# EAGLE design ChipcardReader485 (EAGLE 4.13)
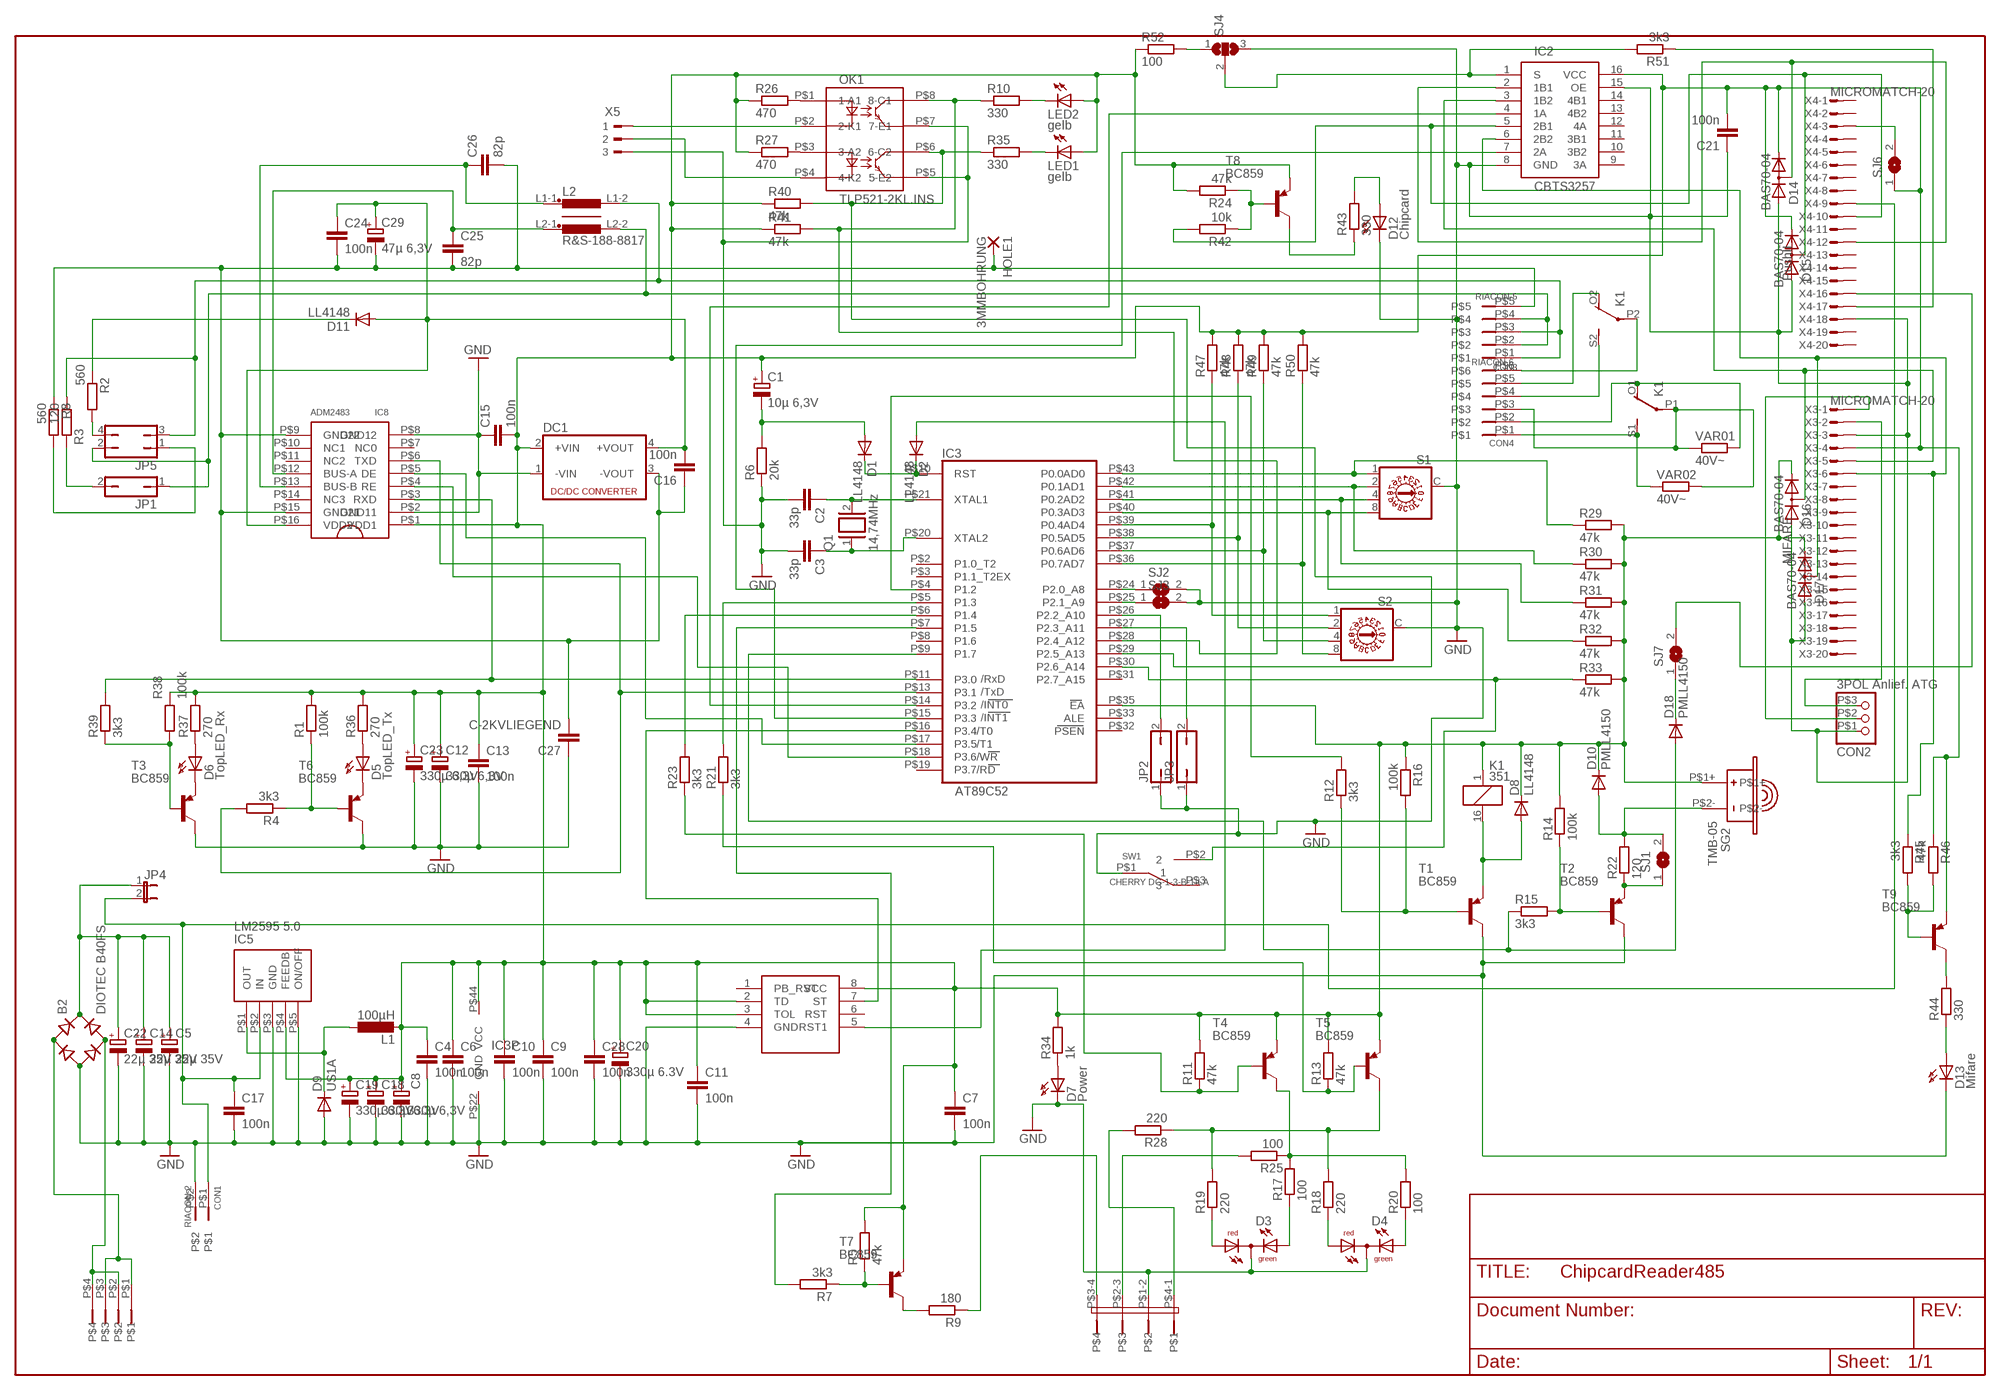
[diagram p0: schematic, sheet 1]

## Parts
B2  DIOTEC B40FS  DIOTECB40FS  [DIOTECB40FS]
C1  10µ 6,3V  CPOL-EUCT3216  [CT3216]
C2  33p  C-EUC0805  [C0805]
C3  33p  C-EUC0805  [C0805]
C4  100n  C-EUC0805  [C0805]
C5  22µ 35V  CPOL-EUCT7343  [CT7343]
C6  100n  C-EUC0805  [C0805]
C7  100n  C-EUC0805  [C0805]
C8  330µ 6,3V  CPOL-EUCT7343  [CT7343]
C9  100n  C-EUC0805  [C0805]
C10  100n  C-EUC0805  [C0805]
C11  100n  C-EUC0805  [C0805]
C12  330µ 6,3V  CPOL-EUCT7343  [CT7343]
C13  100n  C-EUC0805  [C0805]
C14  22µ 35V  CPOL-EUCT7343  [CT7343]
C15  100n  C-EUC0805  [C0805]
C16  100n  C-EUC0805  [C0805]
C17  100n  C-EUC0805  [C0805]
C18  330µ 6.3V  CPOL-EUCT7343  [CT7343]
C19  330µ 6.3V  CPOL-EUCT7343  [CT7343]
C20  330µ 6.3V  CPOL-EUCT7343  [CT7343]
C21  100n  C-EUC0805  [C0805]
C22  22µ 35V  CPOL-EUCT7343  [CT7343]
C23  330µ 6,3V  CPOL-EUCT7343  [CT7343]
C24  100n  C-EUC0805  [C0805]
C25  82p  C-EUC0805  [C0805]
C26  82p  C-EUC0805  [C0805]
C27  C-2KVLIEGEND  [C-2KV-LIEG]
C28  100n  C-EUC0805  [C0805]
C29  47µ 6,3V  CPOL-EUCT6032  [CT6032]
CON1  RIACON-2  [RIACON-2]
CON2  3POL Anlief. ATG  PROGRAMMIER-3POL  [PROGRAMMIER-3POL]
CON3  RIACON-5  [RIACON-5]
CON4  RIACON-6  [RIACON-6]
CON5  RIACON-4  [RIACON-4]
D1  LL4148  PMLL4150  [SOD80C]
D2  LL4148  PMLL4150  [SOD80C]
D3  DUOLED5MM  [DUOLED5MM]
D4  DUOLED5MM  [DUOLED5MM]
D5  TopLED_Tx  LED3MMPLCC-2  [TOPLED]
D6  TopLED_Rx  LED3MMPLCC-2  [TOPLED]
D7  Power  LED3MMPLCC-2  [TOPLED]
D8  LL4148  PMLL4150  [SOD80C]
D9  US1A  DIODE-SOD106A-R  [SOD106A-R]
D10  PMLL4150  [SOD80C]
D11  LL4148  PMLL4150  [SOD80C]
D12  Chipcard  LED3MMPLCC-2  [TOPLED]
D13  Mifare  LED3MMPLCC-2  [TOPLED]
D14  BAS70-04  DIODE_2CACA-SOT23  [SOT23]
D15  BAS70-04  DIODE_2CACA-SOT23  [SOT23]
D16  BAS70-04  DIODE_2CACA-SOT23  [SOT23]
D17  BAS70-04  DIODE_2CACA-SOT23  [SOT23]
D18  PMLL4150  [SOD80C]
DC1  NME  [NME]
HOLE1  3MMBOHRUNG  [3MMBOHRUNG]
IC2  CBTS3257  [SO16]
IC3  AT89C52  [PLCC44-SOCKEL]
IC4  MAX1232  [SO08]
IC5  LM2595 5.0  LM2595TO-263S  [LM2576S]
IC8  ADM2483  [SOIC16W]
JP1  JP1Q  [JP1]
JP2  JP1Q  [JP1]
JP3  JP1Q  [JP1]
JP4  JP1E  [JP1]
JP5  JP2Q  [JP2Q]
JP7  2X2ABGEWINKELT  [2X2ABGEWINKELT]
K1  351  [351]
L1  100µH  DO3316P  [DO3316P]
L2  R&S-188-8817  [R&S-188-8817]
LED1  gelb  LEDSMT1206  [1206]
LED2  gelb  LEDSMT1206  [1206]
OK1  TLP521-2KL.INS  [TLP521-2]
Q1  14,74MHz  XTAL/S  [QS]
R1  100k  R-EU_R0805  [R0805]
R2  560  R-EU_R0805  [R0805]
R3  120  R-EU_R0805  [R0805]
R4  3k3  R-EU_R0805  [R0805]
R5  47k  R-EU_R0805  [R0805]
R6  20k  R-EU_R0805  [R0805]
R7  3k3  R-EU_R0805  [R0805]
R8  560  R-EU_R0805  [R0805]
R9  180  R-EU_R0805  [R0805]
R10  330  R-EU_R0805  [R0805]
R11  47k  R-EU_R0805  [R0805]
R12  3k3  R-EU_R0805  [R0805]
R13  47k  R-EU_R0805  [R0805]
R14  100k  R-EU_R0805  [R0805]
R15  3k3  R-EU_R0805  [R0805]
R16  100k  R-EU_R0805  [R0805]
R17  100  R-EU_R0805  [R0805]
R18  220  R-EU_R0805  [R0805]
R19  220  R-EU_R0805  [R0805]
R20  100  R-EU_R0805  [R0805]
R21  3k3  R-EU_R0805  [R0805]
R22  120  R-EU_R0805  [R0805]
R23  3k3  R-EU_R0805  [R0805]
R24  47k  R-EU_R0805  [R0805]
R25  100  R-EU_R0805  [R0805]
R26  470  R-EU_R0805  [R0805]
R27  470  R-EU_R0805  [R0805]
R28  220  R-EU_R0805  [R0805]
R29  47k  R-EU_R0805  [R0805]
R30  47k  R-EU_R0805  [R0805]
R31  47k  R-EU_R0805  [R0805]
R32  47k  R-EU_R0805  [R0805]
R33  47k  R-EU_R0805  [R0805]
R34  1k  R-EU_R0805  [R0805]
R35  330  R-EU_R0805  [R0805]
R36  270  R-EU_R0805  [R0805]
R37  270  R-EU_R0805  [R0805]
R38  100k  R-EU_R0805  [R0805]
R39  3k3  R-EU_R0805  [R0805]
R40  47k  R-EU_R0805  [R0805]
R41  47k  R-EU_R0805  [R0805]
R42  10k  R-EU_R0805  [R0805]
R43  330  R-EU_R0805  [R0805]
R44  330  R-EU_R0805  [R0805]
R45  3k3  R-EU_R0805  [R0805]
R46  47k  R-EU_R0805  [R0805]
R47  47k  R-EU_R0805  [R0805]
R48  47k  R-EU_R0805  [R0805]
R49  47k  R-EU_R0805  [R0805]
R50  47k  R-EU_R0805  [R0805]
R51  3k3  R-EU_R0805  [R0805]
R52  100  R-EU_R0805  [R0805]
S1  P103  [P103]
S2  P103  [P103]
SG2  TMB-05  [TMB-05]
SJ1  SJ  [SJ]
SJ2  SJ  [SJ]
SJ3  SJ  [SJ]
SJ4  SJ2W  [SJ_2]
SJ6  SJ  [SJ]
SJ7  SJ  [SJ]
SW1  CHERRY DG-1-3-B-1-LA  CHERRI-MICROTASTER  [CHERRI-MICROTASTER]
T1  BC859  BCX71SMD  [SOT23]
T2  BC859  BCX71SMD  [SOT23]
T3  BC859  BCX71SMD  [SOT23]
T4  BC859  BCX71SMD  [SOT23]
T5  BC859  BCX71SMD  [SOT23]
T6  BC859  BCX71SMD  [SOT23]
T7  BC859  BCX71SMD  [SOT23]
T8  BC859  BCX71SMD  [SOT23]
T9  BC859  BCX71SMD  [SOT23]
VAR01  40V~  R-EU_M1206  [M1206]
VAR02  40V~  R-EU_M1206  [M1206]
X3  MICROMATCH-20  [MICROMATCH-20]
X4  MICROMATCH-20  [MICROMATCH-20]
X5  180-3  [180-3]

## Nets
1 [relais]: CON4.P$1 K1.S1(2:S) VAR02.1
2 [relais]: CON4.P$2 K1.O1(2:O) VAR01.2
3 [relais]: CON4.P$3 K1.P1(2:P) VAR01.1 VAR02.2
4 [relais]: CON4.P$4 K1.S2(3:S)
5 [relais]: CON4.P$5 K1.O2(3:O)
6 [relais]: CON4.P$6 K1.P2(3:P)
+B [power]: C17.1 CON1.P$1 IC5.P$2(IN) JP4.2 X4.9
+VO [power]: B2.PLUS(+) C5.+ C14.+ C22.+ JP4.1
A-OUT: C25.1 IC8.P$12(BUS-A) L2.L2-1(W2A)
B-OUT: C26.1 IC8.P$13(BUS-B) L2.L1-1(W1A)
BUS_A: CON3.P$2 CON3.P$4 JP1.1 JP5.2 L2.L2-2(W2E)
BUS_B: CON3.P$1 CON3.P$3 JP5.3 L2.L1-2(W1E) R3.1
CLOCK: IC2.4(1A) IC3.P$14(P3.2)
D3: IC3.P$28(P2.4_A12) OK1.P$8(8-C1) R10.1 R41.2
DATA: IC2.7(2A) IC3.P$15(P3.3)
GND [power]: B2.MINUS(-) C2.2 C3.2 C4.2 C5.- C6.2 C7.2 C8.- C9.2 C10.2 C11.2 C12.- C13.2 C14.- C15.1 C17.2 C18.- C19.- C20.- C21.1 C22.- C23.- C27.P$1 C28.2 CON1.P$2 CON2.P$1 D3.K(C) D4.K(C) D7.K(C) D9.A D12.K(C) D13.K(C) D14.1(A) D15.1(A) D16.1(A) D17.1(A) DC1.1(-VIN) IC2.8(GND) IC2.15(OE) IC3.P$22(GND) IC4.4(GND) IC5.P$3(GND) IC5.P$5(ON/OFF) IC8.P$2(GND11) IC8.P$8(GND12) JP2.1 JP3.1 JP7.P$1-2 OK1.P$5(5-E2) OK1.P$7(7-E1) R6.1 S1.C S2.C SJ2.2 SJ3.2 SJ4.3 SW1.P$1 T1.3(C) T2.3(C) T3.3(C) T6.3(C) X3.3 X4.18 X5.3
GND-BUS [gnd-bus]: C16.1 C24.2 C25.2 C26.2 C27.P$2 C29.- CON3.P$5 DC1.3(-VOUT) HOLE1.P$1(P) IC8.P$9(GND22) IC8.P$15(GND21) R8.1
IN1 [in]: B2.WECHSEL1(AC1) CON5.P$1 CON5.P$3
IN2 [in]: B2.WECHSEL2(AC2) CON5.P$2 CON5.P$4
N$1: IC3.P$39(P0.4AD4) R47.1 S2.1
N$2: IC3.P$38(P0.5AD5) R48.1 S2.2
N$3: IC3.P$37(P0.6AD6) R49.1 S2.4
N$4: LED1.C R35.2
N$5: LED2.C R10.2
N$6: IC3.P$29(P2.5_A13) OK1.P$6(6-C2) R35.1 R40.2
N$7: IC3.P$4(P1.2) R12.2
N$8: JP7.P$3-4 R9.1
N$9: JP5.4 R2.2
N$10: OK1.P$1(1-A1) R26.2
N$11: C3.1 IC3.P$20(XTAL2) Q1.1
N$12: C2.1 IC3.P$21(XTAL1) Q1.2
N$13: D5.A R36.1
N$14: IC3.P$5(P1.3) R21.2
N$15: D5.K(C) T6.2(E)
N$16: JP1.2 R3.2
N$17: OK1.P$3(3-A2) R27.2
N$18: JP5.1 R8.2
N$19: IC3.P$36(P0.7AD7) R50.1 S2.8
N$20: D6.K(C) T3.2(E)
N$21: R11.1 R23.1 T4.1(B)
N$22: D6.A R37.1
N$23: R38.1 R39.1 T3.1(B)
N$24: IC2.1(S) R51.2 SJ4.2
N$25: IC3.P$30(P2.6_A14) R33.1 SW1.P$2
N$26: R12.1 R16.2 T1.1(B)
N$27: D1.C D2.C IC3.P$10(RST)
N$28: R22.1 SJ1.1 T2.2(E)
N$29: C1.- D1.A R6.2
N$30: D3.AR R19.1
N$31: D3.AG R17.1
N$32: R1.1 R4.1 T6.1(B)
N$34: D4.AR R18.1
N$35: IC3.P$6(P1.4) R23.2
N$36: D2.A IC4.5(RST1)
N$37: R14.1 R15.2 T2.1(B)
N$38: IC3.P$40(P0.3AD3) R32.1 S1.8
N$39: C16.2 C24.1 C29.+ D11.A DC1.4(+VOUT) IC8.P$16(VDD2)
N$40: R5.1 R7.1 T7.1(B)
N$41: D4.AG R20.1
N$42: IC3.P$16(P3.4/T0) IC4.7(ST)
N$43: IC3.P$41(P0.2AD2) R31.1 S1.4
N$44: D7.A R34.1
N$45: IC3.P$42(P0.1AD1) R30.1 S1.2
N$46: IC3.P$43(P0.0AD0) R29.1 S1.1
N$47: R13.1 R21.1 T5.1(B)
N$48: R18.2 R19.2 R28.1 T5.3(C)
N$49: R9.2 T7.3(C)
N$50: D18.A IC3.P$9(P1.7) R15.1
N$51: D10.A R22.2 SG2.P$2- SJ1.2
N$52: R17.2 R20.2 R25.1 T4.3(C)
N$53: IC3.P$7(P1.5) R7.2
N$54: IC3.P$24(P2.0_A8) SJ2.1
N$55: IC3.P$25(P2.1_A9) SJ3.1
N$56: IC3.P$18(P3.6/WR) IC8.P$4(RE)
N$57: D15.3(AC) IC2.5(2B1) R42.2 X4.10
N$58: JP7.P$2-3 R25.2
N$59: D14.3(AC) IC2.2(1B1) X4.12
N$60: IC3.P$26(P2.2_A10) JP2.2
N$61: IC3.P$27(P2.3_A11) JP3.2
N$62: D8.A K1.16 T1.2(E)
N$63: CON2.P$2 X3.1
N$64: JP7.P$4-1 R28.2
N$65: D17.3(AC) IC2.6(2B2) R45.1 X3.6
N$66: D16.3(AC) IC2.3(1B2) X3.5
N$67 [power]: SJ6.2 X4.3
N$68: R52.2 SJ4.1
N$69: D12.A R43.2
N$70: R43.1 T8.3(C)
N$71: R24.1 R42.1 T8.1(B)
N$72: SJ7.2 X4.16
N$73: D13.A R44.1
N$74: CON2.P$3 X3.2
N$75: R44.2 T9.3(C)
N$76: OK1.P$4(4-K2) X5.2
N$77: OK1.P$2(2-K1) X5.1
N$78: R45.2 R46.2 T9.1(B)
N$79: R51.1 X4.17
N$80: D11.C R2.1
N$81: D18.C SJ7.1
RX/TX: IC3.P$17(P3.5/T1) IC8.P$5(DE)
RXD: IC3.P$11(P3.0) IC8.P$3(RXD) R39.2
S1 [p]: D9.C IC5.P$1(OUT) L1.2
TXD: IC3.P$13(P3.1) IC8.P$6(TXD) R4.2
VCC [power]: C1.+ C4.1 C6.1 C7.1 C8.+ C9.1 C10.1 C11.1 C12.+ C13.1 C15.2 C18.+ C19.+ C20.+ C21.2 C23.+ C28.1 D8.C D10.C D14.2(C) D15.2(C) D16.2(C) D17.2(C) DC1.2(+VIN) IC2.16(VCC) IC3.P$35(EA) IC3.P$44(VCC) IC4.2(TD) IC4.3(TOL) IC4.8(VCC) IC5.P$4(FEEDB) IC8.P$1(VDD1) K1.1 L1.1 LED1.A LED2.A R1.2 R5.2 R11.2 R13.2 R14.2 R16.1 R24.2 R26.1 R27.1 R29.2 R30.2 R31.2 R32.2 R33.2 R34.2 R36.2 R37.2 R38.2 R40.1 R41.1 R46.1 R47.2 R48.2 R49.2 R50.2 R52.1 SG2.P$1+ SJ6.1 T4.2(E) T5.2(E) T7.2(E) T8.2(E) T9.2(E) X3.4
Unconnected: IC2.9(3A) IC2.10(3B2) IC2.11(3B1) IC2.12(4A) IC2.13(4B2) IC2.14(4B1) IC3.P$2(P1.0_T2) IC3.P$3(P1.1_T2EX) IC3.P$8(P1.6) IC3.P$19(P3.7/RD) IC3.P$31(P2.7_A15) IC3.P$32(PSEN) IC3.P$33(ALE) IC4.1(PB_RST) IC4.6(RST) IC8.P$7(NC0) IC8.P$10(NC1) IC8.P$11(NC2) IC8.P$14(NC3) SW1.P$3 X3.7 X3.8 X3.9 X3.10 X3.11 X3.12 X3.13 X3.14 X3.15 X3.16 X3.17 X3.18 X3.19 X3.20 X4.1 X4.2 X4.4 X4.5 X4.6 X4.7 X4.8 X4.11 X4.13 X4.14 X4.15 X4.19 X4.20

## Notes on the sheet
- PushII
- MIFARE

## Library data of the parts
B2 = rectifier:DIOTECB40FS
C1 C5 C8 C12 C14 C18-C20 C22 C23 C29 = rcl:CPOL-EU: POLARIZED CAPACITOR, European symbol
C2-C4 C6 C7 C9-C11 C13 C15-C17 C21 C24-C26 C28 = rcl:C-EU: CAPACITOR, European symbol
C27 = capacitor-wima:C-2KV
CON1 = con-riacon:RIACON-2
CON2 = pinhead:PROGRAMMIER-3POL
CON3 = con-riacon:RIACON-5
CON4 = con-riacon:RIACON-6
CON5 = con-riacon:RIACON-4
D1 D2 D8 D10 D11 D18 = diode:PMLL4150: DIODE
D3 D4 = led:DUOLED5MM: DUO LED 2 colors, 5 mm, round
D5-D7 D12 D13 = led:LED3MM: LED
D9 = diode:DIODE-: DIODE
D14-D17 = diode:DIODE_2CACA-: 2 Diodes - Cathode-Anode|Cathode-Anode
DC1 = dc-dc-converter:NME: DC-DC CONVERTER
HOLE1 = wirepad:3MMBOHRUNG
IC2 = PHILIPS:CBTS3257: Der Switcher
IC3 = atmel:AT89C*52: MICROCONTROLLER 8 Kbytes FLASH; 2K Bytes EEPROM Compatible with MCS-51 Products at89s8252.pdf
IC4 = watch:MAX1232
IC5 = National_Semiconductor:LM2595: SIMPLE SWITCHER® Power Converter 150 kHz 1A Step-Down Voltage Regulator
IC8 = analog-devices:ADM2483: Isolated RS-485 Transciver with I-Coupler
JP1-JP3 = jumper:JP1Q: JUMPER
JP4 = jumper:JP1E: JUMPER
JP5 = jumper:JP2Q: JUMPER
JP7 = jumper:2X2ABGEWINKELT
K1 = relay:351: RELAY 2 x switch, Omron
L1 = inductor-coilcraft:DO3316P: COILCRAFT
L2 = inductors:R&S-188-8817: Filterspule von R&S
LED1 LED2 = led:LED: LED
OK1 = optocoupler:TLP521-2
Q1 = special:XTAL/S: CRYSTAL
R1-R52 VAR01 VAR02 = rcl:R-EU_: RESISTOR, European symbol
S1 S2 = switch-dil:P103: DIL/CODE SWITCH
SG2 = buzzer:TMB-05
SJ1-SJ3 SJ6 SJ7 = jumper:SJ: SMD solder JUMPER
SJ4 = jumper:SJ2W: SMD solder JUMPER
SW1 = switch:CHERRI-MICROTASTER
T1-T9 = transistor-pnp:BCX71SMD: PNP Transistor
X3 X4 = con-amp-micromatch:MICROMATCH-20: MicroMaTch 20 9-215464-0 / 2-215464-0 Drawing Number C-215464 DDEController.pdf
X5 = con-weidmueller-sl35:180-3: WEIDMUELLER CLAMP CONNECTOR

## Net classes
1 relais: width 0.61 mm
2 power: width 0.508 mm
3 p: width 0.66 mm
4 in: width 0.559 mm
5 gnd-bus: width 0.406 mm

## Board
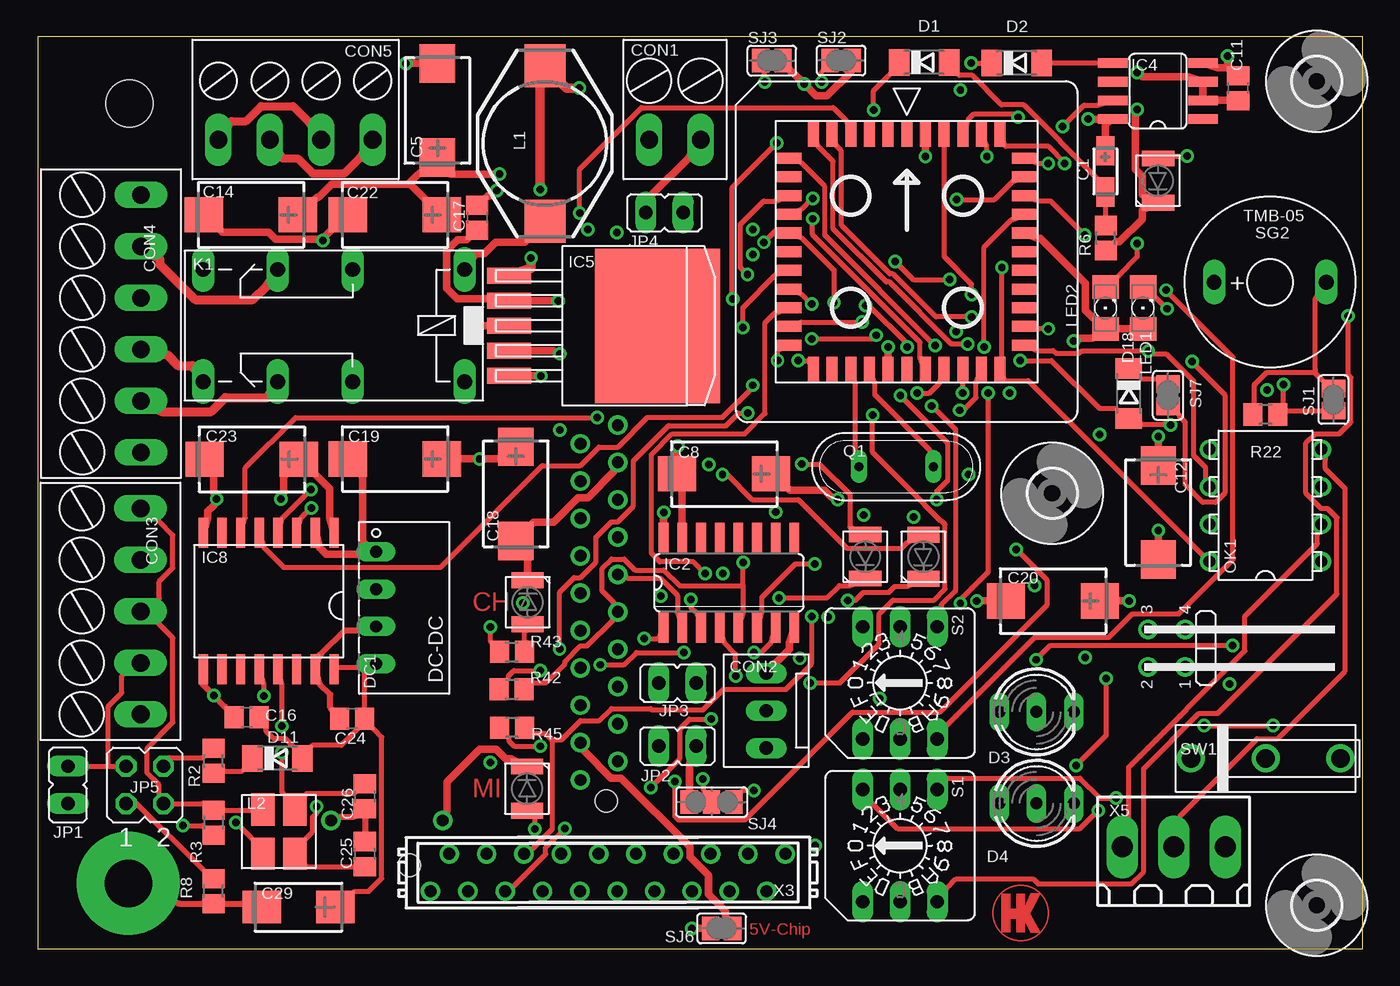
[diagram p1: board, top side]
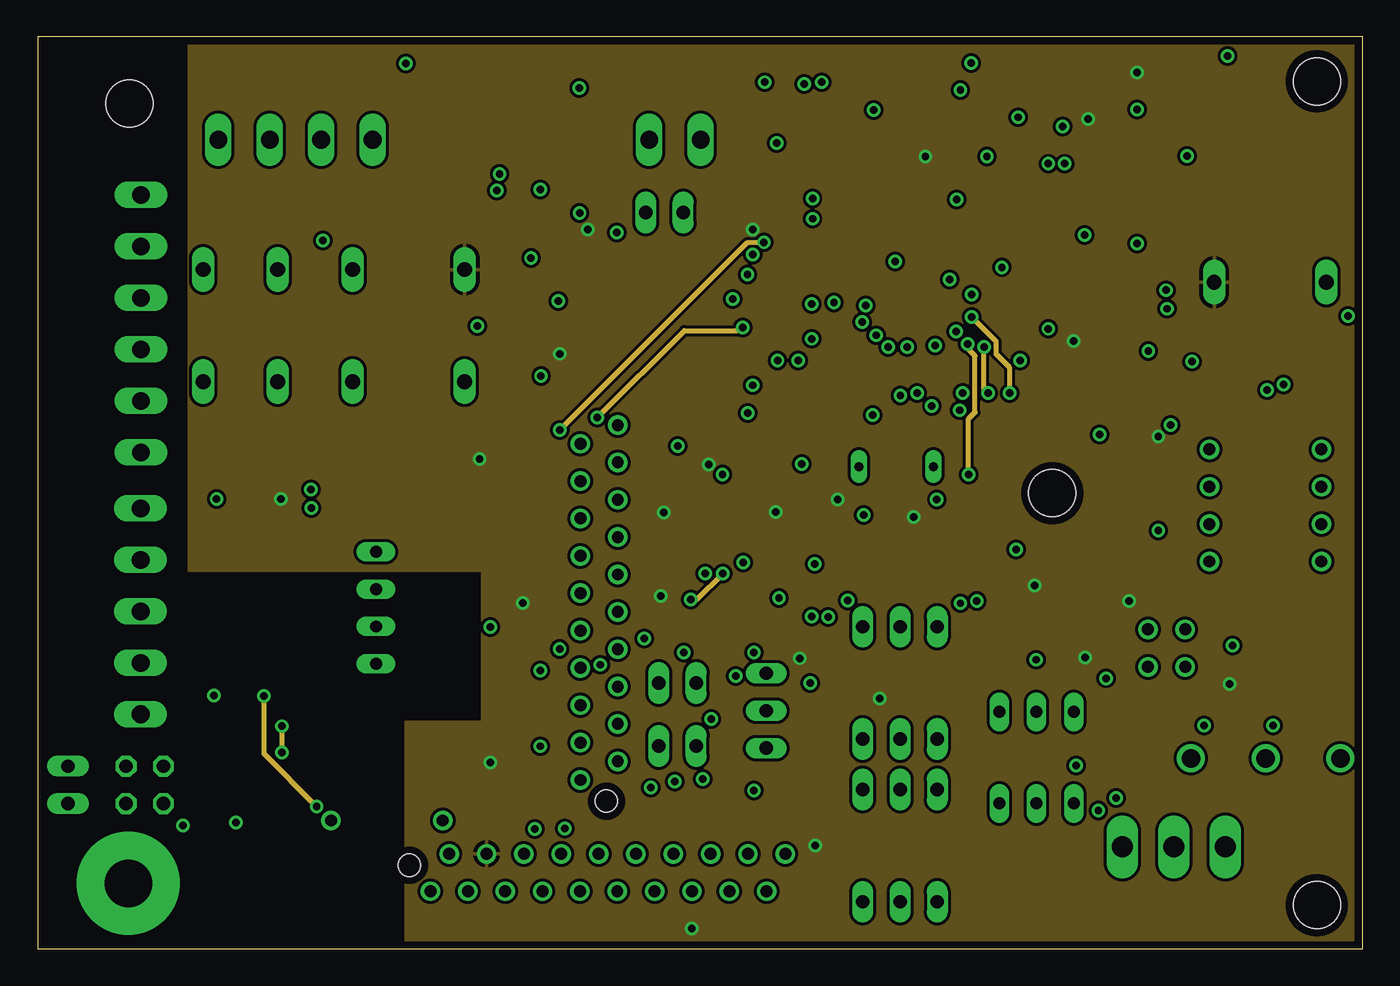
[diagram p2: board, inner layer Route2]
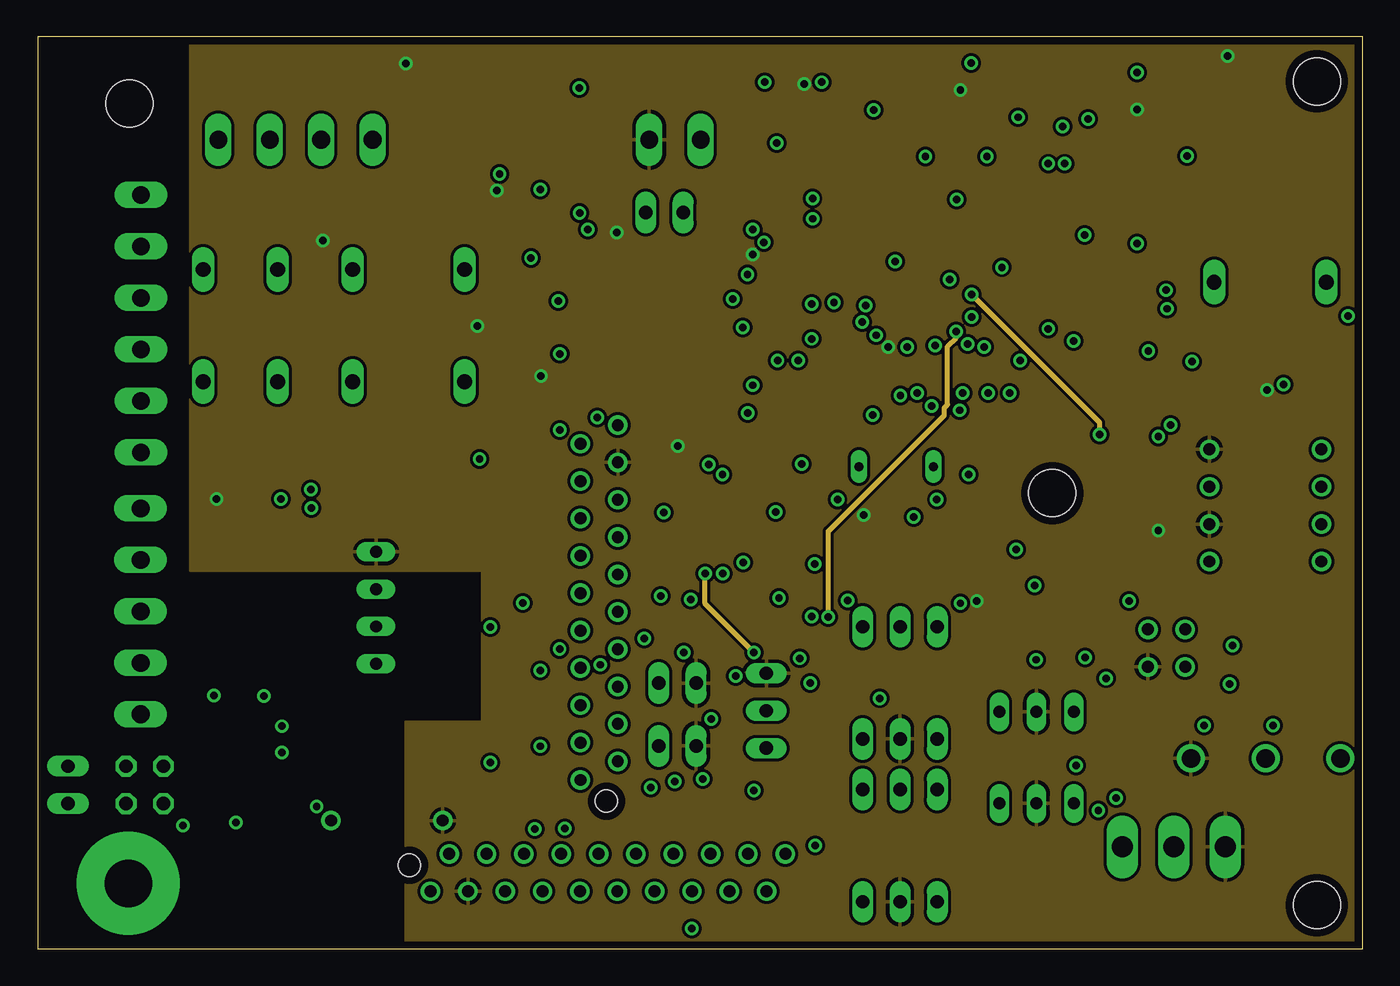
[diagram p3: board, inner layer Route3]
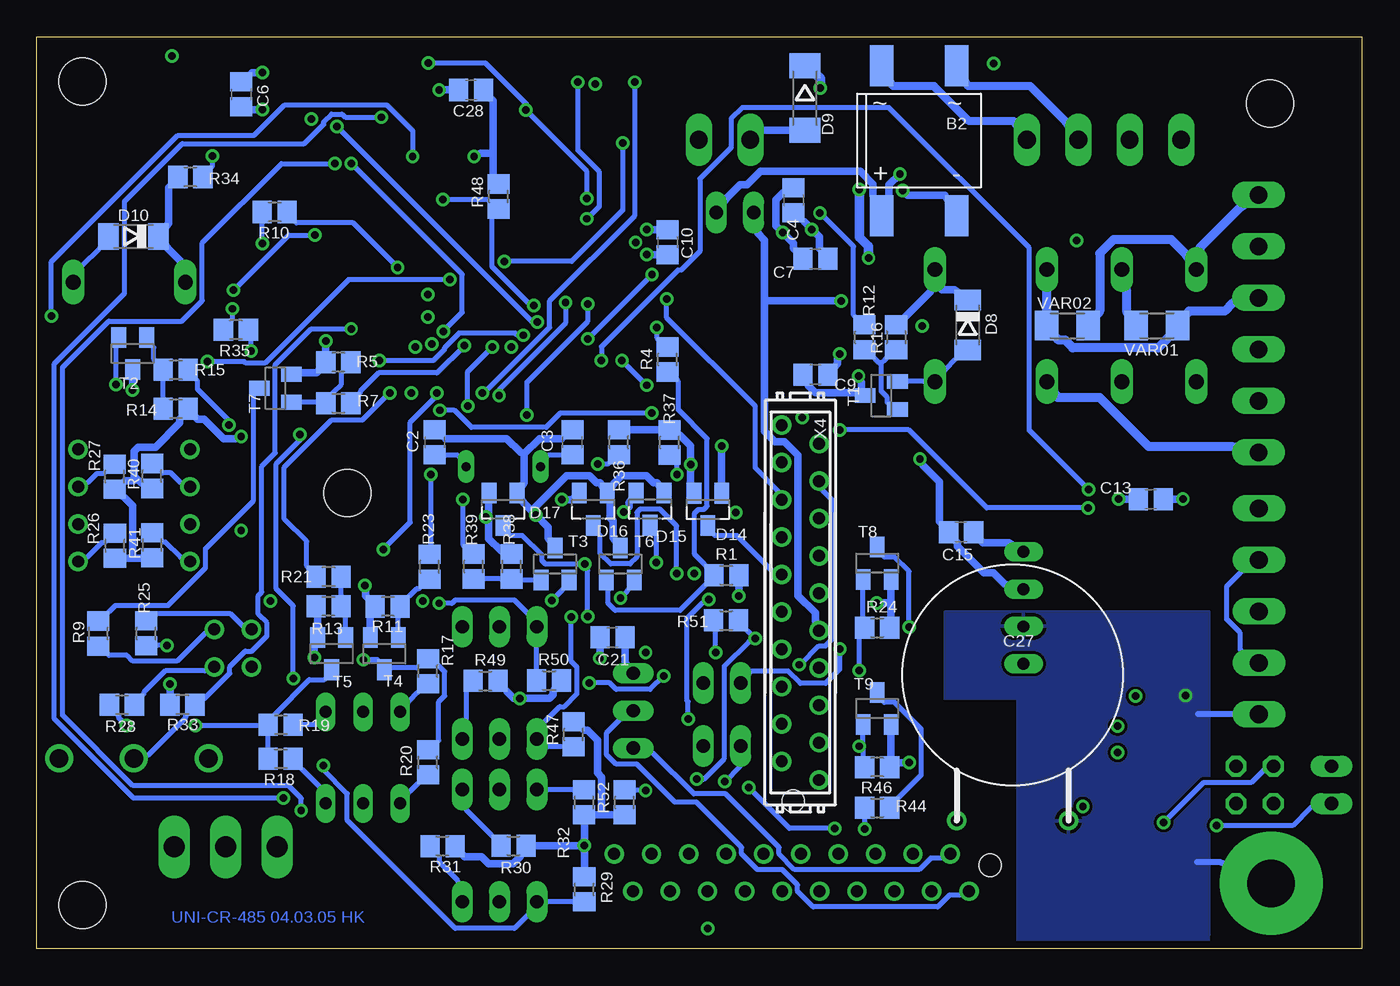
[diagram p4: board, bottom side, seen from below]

Size 90.12 x 62 mm. Coordinates in mm from the lower left corner, seen from the top.
Outline: 90.12,0 90.12,62 0,62 0,0 90.12,0
Copper layers (1+2+3*16): Top 0.035mm / dielectric 0.35mm / Route2 0.035mm / dielectric 0.71mm / Route3 0.035mm / dielectric 0.35mm / GND 0.035mm
Design rules "default": minimum track width 14mil, minimum drill 20mil, track to track 8mil, track to pad 8mil, pad to pad 8mil, via to via 8mil, smd to smd 8mil, copper to edge 20mil, drill to drill 12mil, minimum pad ring 10mil, minimum via ring 8mil, stop-mask expansion 4mil, vias tented up to drill 0mil, thermal gap 10mil
Holes 3.2 mm at 6.25,57.47
tRestrict: area 0.9,53.3 to 10.1,62; area 0,0.1 to 2.5,8.5; area 2.6,0 to 10.3,0.9
bRestrict: area 1,53.3 to 10.2,62; area 0,0.1 to 2.5,8.5; area 2.6,0 to 10.3,0.9

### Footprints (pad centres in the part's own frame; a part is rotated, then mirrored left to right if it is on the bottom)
DIOTECB40FS = smd 1.6 x 2.8: MINUS 2.55,-5.1; PLUS -2.55,-5.1; WECHSEL1 -2.55,5.1; WECHSEL2 2.55,5.1
CT3216 = smd 2 x 1.2: + 1.4,0; - -1.4,0
C0805 = smd 1.3 x 1.5: 1 -0.85,0; 2 0.85,0
CT7343 = smd 2.6 x 2.4: + 3.2,0; - -3.2,0
C-2KV-LIEG = drill 0.813 round: P$1 -3.8,-0.4; P$2 3.8,-0.4
CT6032 = smd 2.6 x 2.2: + 2.5,0; - -2.5,0
RIACON-2 = drill 1.2 long: P$1 0,1.75; P$2 0,-1.75
PROGRAMMIER-3POL = drill 0.9 long: P$1 0,2.54; P$2 0,0; P$3 0,-2.54
RIACON-5 = drill 1.2 long: P$1 0,7; P$2 0,3.5; P$3 0,0; P$4 0,-3.5; P$5 0,-7
RIACON-6 = drill 1.2 long: P$1 0,8.75; P$2 0,5.25; P$3 0,1.75; P$4 0,-1.75; P$5 0,-5.25; P$6 0,-8.75
RIACON-4 = drill 1.2 long: P$1 0,5.25; P$2 0,1.75; P$3 0,-1.75; P$4 0,-5.25
SOD80C = smd 1.4 x 1.8: A 1.7,0; C -1.7,0
DUOLED5MM = drill 0.813 long: AG -2.54,0; AR 2.54,0; K 0,0
TOPLED = smd 2.184 x 1.067: A 0,1.5; K 0,-1.5
SOD106A-R = smd 1.7 x 2.1: A 2.2,0; C -2.2,0
SOT23 = smd 1 x 1.4: 1 -0.95,-1.1; 2 0.95,-1.1; 3 0,1.1
NME = drill 0.813 long: 1 0,3.81; 2 0,1.27; 3 0,-1.27; 4 0,-3.81
3MMBOHRUNG = drill 3.2 pad 7 round: P$1 0,0
SO16 = smd 0.66 x 2.032: 1 -4.445,-3.073; 2 -3.175,-3.073; 3 -1.905,-3.073; 4 -0.635,-3.073; 5 0.635,-3.073; 6 1.905,-3.073; 7 3.175,-3.073; 8 4.445,-3.073; 9 4.445,3.073; 10 3.175,3.073; 11 1.905,3.073; 12 0.635,3.073; 13 -0.635,3.073; 14 -1.905,3.073; 15 -3.175,3.073; 16 -4.445,3.073
PLCC44-SOCKEL = smd 0.75 x 1.8: P$1 0,8.05; P$2 -1.27,8.05; P$3 -2.54,8.05; P$4 -3.81,8.05; P$5 -5.08,8.05; P$6 -6.35,8.05; P$18 -6.35,-8.05; P$19 -5.08,-8.05; P$20 -3.81,-8.05; P$21 -2.54,-8.05; P$22 -1.27,-8.05; P$23 0,-8.05; P$24 1.27,-8.05; P$25 2.54,-8.05; P$26 3.81,-8.05; P$27 5.08,-8.05; P$28 6.35,-8.05; P$40 6.35,8.05; P$41 5.08,8.05; P$42 3.81,8.05; P$43 2.54,8.05; P$44 1.27,8.05 | smd 1.8 x 0.75: P$7 -8.05,6.35; P$8 -8.05,5.08; P$9 -8.05,3.81; P$10 -8.05,2.54; P$11 -8.05,1.27; P$12 -8.05,0; P$13 -8.05,-1.27; P$14 -8.05,-2.54; P$15 -8.05,-3.81; P$16 -8.05,-5.08; P$17 -8.05,-6.35; P$29 8.05,-6.35; P$30 8.05,-5.08; P$31 8.05,-3.81; P$32 8.05,-2.54; P$33 8.05,-1.27; P$34 8.05,0; P$35 8.05,1.27; P$36 8.05,2.54; P$37 8.05,3.81; P$38 8.05,5.08; P$39 8.05,6.35
SO08 = smd 0.66 x 2.032: 1 -1.905,-3.073; 2 -0.635,-3.073; 3 0.635,-3.073; 4 1.905,-3.073; 5 1.905,3.073; 6 0.635,3.073; 7 -0.635,3.073; 8 -1.905,3.073
LM2576S = smd 3 x 1.067: P$1 6.38,-3.4; P$2 6.38,-1.7; P$3 6.38,0; P$4 6.38,1.7; P$5 6.38,3.4 | smd 8.5 x 10.5: P$6 -3.72,0
SOIC16W = smd 0.635 x 2.032: P$1 -4.445,-4.645; P$2 -3.175,-4.645; P$3 -1.905,-4.645; P$4 -0.635,-4.645; P$5 0.635,-4.645; P$6 1.905,-4.645; P$7 3.175,-4.645; P$8 4.445,-4.645; P$9 4.445,4.645; P$10 3.175,4.645; P$11 1.905,4.645; P$12 0.635,4.645; P$13 -0.635,4.645; P$14 -1.905,4.645; P$15 -3.175,4.645; P$16 -4.445,4.645
JP1 = drill 0.914 long: 1 0,-1.27; 2 0,1.27
JP2Q = drill 0.914 octagon: 1 -1.27,-1.27; 2 -1.27,1.27; 3 1.27,-1.27; 4 1.27,1.27
2X2ABGEWINKELT = drill 0.813 round: P$1-2 -1.27,2.54; P$2-3 1.27,2.54; P$3-4 1.27,0; P$4-1 -1.27,0
351 = drill 1.016 long: 1 -3.81,-3.81; 16 -3.81,3.81; O1 8.89,-3.81; O2 8.89,3.81; P1 3.81,-3.81; P2 3.81,3.81; S1 13.97,-3.81; S2 13.97,3.81
DO3316P = smd 2.92 x 2.79: 1 -5.28,0; 2 5.28,0
R&S-188-8817 = smd 2.2 x 1.6: L1-1 -1.5,1.1; L1-2 -1.5,-1.1; L2-1 1.5,1.1; L2-2 1.5,-1.1
1206 = smd 1.6 x 1.803: A -1.422,0; C 1.422,0
TLP521-2 = drill 0.813 round: P$1 -3.81,-3.81; P$2 -1.27,-3.81; P$3 1.27,-3.81; P$4 3.81,-3.81; P$5 3.81,3.81; P$6 1.27,3.81; P$7 -1.27,3.81; P$8 -3.81,3.81
QS = drill 0.61 long: 1 -2.54,0; 2 2.54,0
R0805 = smd 1.3 x 1.5: 1 -0.85,0; 2 0.85,0
P103 = drill 0.914 long: 1 3.81,-2.54; 2 -3.81,2.54; 4 3.81,2.54; 8 -3.81,-2.54; C 3.81,0; C1 -3.81,0
TMB-05 = drill 1.016 long: P$1+ -3.81,0; P$2- 3.81,0
SJ = smd 1.168 x 1.6: 1 -0.762,0; 2 0.762,0
SJ_2 = smd 1.168 x 1.6: 1 -1.524,0; 2 0,0; 3 1.524,0
CHERRI-MICROTASTER = drill 1.27 round: P$1 -5.08,0; P$2 0,0; P$3 5.08,0
3,2 = hole 3.2: 0,0
M1206 = smd 1.6 x 2: 1 -1.4,0; 2 1.4,0
MICROMATCH-20 = drill 0.813 round: 1 12.065,1.27; 2 10.795,-1.27; 3 9.525,1.27; 4 8.255,-1.27; 5 6.985,1.27; 6 5.715,-1.27; 7 4.445,1.27; 8 3.175,-1.27; 9 1.905,1.27; 10 0.635,-1.27; 11 -0.635,1.27; 12 -1.905,-1.27; 13 -3.175,1.27; 14 -4.445,-1.27; 15 -5.715,1.27; 16 -6.985,-1.27; 17 -8.255,1.27; 18 -9.525,-1.27; 19 -10.795,1.27; 20 -12.065,-1.27 | hole 1.5: 13.5,-0.5
180-3 = drill 1.422 long: 1 -3.5,0; 2 0,0; 3 3.5,0

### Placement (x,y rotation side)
B2  30.12,54.94 0 bottom
C1  72.62,52.85 90 top
C2  63.06,34.43 90 bottom
C3  53.69,34.43 90 bottom
C4  38.65,50.89 90 bottom
C5  27.19,56.99 270 top
C6  76.21,58.09 270 bottom
C7  37.16,46.9 180 bottom
C8  46.68,32.29 0 top
C9  37.16,39.03 180 bottom
C10  47.22,48.03 270 bottom
C11  81.64,58.51 90 top
C12  76.22,29.66 90 top
C13  14.36,30.56 0 bottom
C14  14.51,49.9 0 top
C15  27.26,28.33 180 bottom
C16  14.23,15.74 0 top
C17  29.9,49.7 90 top
C18  32.53,30.93 90 top
C19  24.3,33.3 0 top
C20  69.05,23.65 0 top
C21  50.97,21.17 180 bottom
C22  24.3,49.9 0 top
C23  14.57,33.28 0 top
C24  21.39,15.65 180 top
C25  22.26,6.44 90 top
C26  22.26,10.36 270 top
C27  23.76,9.12 0 bottom
C28  60.59,58.38 180 bottom
C29  17.75,2.83 0 top
CON1  43.35,55 270 top
CON2  49.56,16.19 0 top
CON3  7.01,22.94 0 top
CON4  7.04,42.5 0 top
CON5  17.54,55 270 top
D1  60.28,60.26 0 top
D2  66.57,60.22 0 top
D3  67.94,16.11 0 top
D4  67.94,9.89 0 top
D5  56.29,26.66 0 top
D6  60.24,26.65 0 top
D7  76.2,52.22 0 top
D8  26.8,42.41 270 bottom
D9  37.88,57.83 270 bottom
D10  83.54,48.43 180 bottom
D11  16.3,12.95 0 top
D12  33.33,23.56 180 top
D13  33.28,10.89 180 top
D14  44.48,29.87 180 bottom
D15  48.41,29.89 180 bottom
D16  52.28,29.88 180 bottom
D17  58.41,29.88 180 bottom
D18  74.21,37.74 270 top
DC1  23.02,23.18 0 top
HOLE1  6.18,4.44 0 top
IC2  47.02,24.89 0 top
IC3  59.11,47.39 0 top
IC4  76.19,58.31 90 top
IC5  38.45,42.35 180 top
IC8  15.72,23.64 180 top
JP1  2.08,11.14 180 top
JP2  43.52,13.79 90 top
JP3  43.52,18.06 90 top
JP4  42.64,50.04 90 top
JP5  7.29,11.14 0 top
JP7  78.05,20.44 90 top
K1  25.23,42.37 180 top
L1  34.5,54.75 90 top
L2  16.41,7.96 270 top
LED1  75.17,43.56 90 top
LED2  72.63,43.56 90 top
OK1  83.5,30.14 90 top
Q1  58.38,32.78 0 top
R1  43.22,25.4 0 bottom
R2  11.97,12.77 90 top
R3  11.97,8.57 270 top
R4  47.22,40.06 90 bottom
R5  69.61,39.88 180 bottom
R6  72.64,48.32 90 top
R7  69.61,37.09 0 bottom
R8  11.96,3.92 90 top
R9  85.93,21.43 90 bottom
R10  73.94,50.09 180 bottom
R11  66.25,23.27 180 bottom
R12  33.84,41.57 90 bottom
R13  70.28,23.28 180 bottom
R14  80.66,36.72 0 bottom
R15  80.67,39.35 180 bottom
R16  31.67,41.57 270 bottom
R17  63.52,18.87 90 bottom
R18  73.53,12.91 180 bottom
R19  73.53,15.22 180 bottom
R20  63.52,12.67 90 bottom
R21  70.27,25.29 180 bottom
R22  83.5,36.32 180 top
R23  63.41,25.97 90 bottom
R24  32.97,21.82 0 bottom
R25  82.68,21.44 90 bottom
R26  84.8,27.4 90 bottom
R27  84.82,32.1 90 bottom
R28  84.33,16.6 0 bottom
R29  52.89,4.04 90 bottom
R30  57.71,7 0 bottom
R31  62.53,6.98 0 bottom
R32  52.91,9.96 270 bottom
R33  80.22,16.6 180 bottom
R34  79.67,52.47 180 bottom
R35  76.58,42.08 180 bottom
R36  50.53,34.43 90 bottom
R37  47.09,34.42 90 bottom
R38  57.82,25.99 90 bottom
R39  60.42,25.99 90 bottom
R40  82.28,32.14 90 bottom
R41  82.26,27.44 90 bottom
R42  32.24,17.65 0 top
R43  32.26,20.18 0 top
R44  32.97,9.58 0 bottom
R45  32.26,15.04 180 top
R46  32.97,12.35 180 bottom
R47  53.61,14.58 90 bottom
R48  58.72,51.14 90 bottom
R49  59.61,18.21 0 bottom
R50  55.28,18.24 0 bottom
R51  43.24,22.32 0 bottom
R52  50.15,9.95 90 bottom
S1  58.65,7.01 270 top
S2  58.65,18.08 270 top
SG2  83.82,45.32 0 top
SJ1  88.13,37.33 90 top
SJ2  54.65,60.39 0 top
SJ3  49.94,60.38 0 top
SJ4  45.84,9.97 180 top
SJ6  46.52,1.39 0 top
SJ7  76.87,37.63 270 top
SW1  83.52,12.94 0 top
T1  32.69,37.61 90 bottom
T2  83.6,40.47 180 bottom
T3  54.87,26.16 0 bottom
T4  66.48,20.07 180 bottom
T5  70.07,20.07 180 bottom
T6  50.43,26.16 0 bottom
T7  73.89,38.11 90 bottom
T8  32.97,26.21 0 bottom
T9  32.97,16.33 0 bottom
U$1  [HK]  66.86,2.43 0 top
U$12  [3,2]  87,2.97 0 top
U$13  [3,2]  69,30.97 0 top
U$14  [3,2]  87,58.97 0 top
VAR01  13.95,42.36 180 bottom
VAR02  20.03,42.36 180 bottom
X3  38.79,5.18 180 top
X4  38.19,23.54 270 bottom
X5  77.26,6.93 0 top

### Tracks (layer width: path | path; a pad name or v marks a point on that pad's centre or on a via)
1
  GND 0.61: VAR02.1 17.84,43.35 17.84,47.27 16.9,48.21 12.98,48.21 12.02,47.25 K1.S1 11,47.69 8.32,50.37 CON4.P$1
2
  Top 0.61: CON4.P$2 8.32,46.87 8.32,46.53 10.72,44.13 14.64,44.13 15.6,45.09 K1.O1
  GND 0.61: VAR01.2 16.02,43.35 16.02,44.67 K1.O1
3
  GND 0.61: K1.P1 21.44,44.67 21.44,43.35 VAR02.2 20.64,41.37 20.18,41.37 19.66,40.85 13.86,40.85 13.34,41.37 VAR01.1 11.76,43.35 9.34,43.35 8.82,43.87 CON4.P$3
4
  Top 0.61: K1.S2 10.52,39.65 9.54,39.65 8.82,40.37 CON4.P$4
5
  Top 0.61: K1.O2 15.6,37.47 12.76,37.47 11.8,36.51 8.46,36.51 CON4.P$5
6
  GND 0.61: K1.P2 20.68,37.47 17.84,37.47 14.5,34.13 8.82,34.13 CON4.P$6
+B  (via drill 0.51)
  Top 0.508: C17.1 29.16,48.21 28.56,48.21 27.82,47.47 27.82,44.89 28.52,44.19 30.58,44.19 IC5.P$2 v35.42,44.05 | CON1.P$1 44.22,53.71 41.8,51.29 JP4.2
  GND 0.508: 40.62,44.05 40.62,48.17 41.08,48.63 JP4.2 | 40.62,44.05 40.62,35.17 39.92,34.47 39.26,34.47 38.34,33.55 38.34,23.99 37.18,22.83 37.18,22.29 X4.9 | 40.62,44.05 v35.42,44.05
+VO  (via drill 0.51)
  Top 0.508: 25.2,51.97 20,51.97 19.12,51.09 19,51.09 C14.+ | 25.2,51.97 25.74,52.51 C5.+ 28.1,52.67 v31.42,52.67 | C22.+ 26.22,51.09 25.44,51.87 25.2,51.97
  GND 0.508: JP4.1 43.2,51.03 42.3,51.93 41.82,51.93 40.9,52.85 34.12,52.85 33.26,51.99 33.26,51.23 B2.PLUS 32.16,51.23 32.16,51.93 v31.42,52.67
A-OUT  (via drill 0.51)
  Top 0.356: C25.1 18.3,5.59 L2.L2-1 18.3,7.55 18.7,7.95 18.7,8.95 18.98,9.23 v18.98,9.67 | v15.4,17.17 15.4,17.99 IC8.P$12
  Route2 0.356: v15.4,17.17 15.4,13.25 v18.98,9.67
B-OUT  (via drill 0.51)
  Top 0.356: C26.1 21.52,10.57 18.32,10.57 18.3,10.55 L2.L1-1 16.72,10.55 16.62,10.65 v16.62,13.33 | v16.62,15.13 16.62,17.99 IC8.P$13
  Route2 0.356: v16.62,13.33 v16.62,15.13
BUS_A  (via drill 0.51)
  Top 0.356: v13.48,8.59 14.52,7.55 L2.L2-2 | JP1.1 4.82,12.41 | 4.82,12.41 JP5.2 | CON3.P$4 5.74,18.55 5.74,17.41 4.82,16.49 4.82,12.41
  GND 0.356: CON3.P$4 8.28,20.33 8.28,21.47 9.2,22.39 9.2,24.63 8.28,25.55 CON3.P$2 | v13.48,8.59 10.78,11.29 7.54,11.29 6.72,12.11 JP5.2
BUS_B
  Top 0.356: L2.L1-2 14.52,9.43 12.7,9.43 R3.1 11.22,9.87 JP5.3 8.26,10.57 8.26,11.15 7.46,11.95 7.46,13.65 9.2,15.39 9.2,21.13 8.28,22.05 CON3.P$3 8.28,23.83 8.28,24.97 9.2,25.89 9.2,28.13 8.28,29.05 CON3.P$1
CLOCK  (via drill 0.51)
  Top 0.356: v52.64,43.83 51.98,44.49 51.94,44.49 IC3.P$14 | v56.78,36.29 56.78,33.75 60.32,30.21 60.32,30.19 61.44,29.07 61.5,29.07 61.72,28.85 61.72,24.45 60.98,23.71 58.18,23.71 57.22,22.75 57.22,20.71 54.58,18.07 v52.54,18.07 | v47.48,18.55 47.48,20.03 46.7,20.81 IC2.4
  GND 0.356: v52.64,43.83 52.64,42.67 56.78,38.53 v56.78,36.29 | v52.54,18.07 51.16,18.07 50.72,17.63 48.4,17.63 v47.48,18.55
D3  (via drill 0.51)
  Top 0.356: v65.58,46.33 65.58,40.23 IC3.P$28 65.82,38.63 67.38,38.63 79.22,26.79 OK1.P$8
  GND 0.356: R41.2 81.52,27.65 81.38,27.65 80.34,26.61 OK1.P$8 | v65.58,46.33 68.6,49.35 72.46,49.35 R10.1
DATA  (via drill 0.51)
  Top 0.356: v45.4,25.51 44.6,26.31 42.32,26.31 41.74,26.89 41.74,33.59 43.16,35.01 48.1,35.01 49.48,36.39 49.48,42.57 50.12,43.21 50.18,43.21 IC3.P$15 | v48.72,20.13 49.2,20.13 49.88,20.81 IC2.7
  Route3 0.356: v45.4,25.51 45.4,23.45 v48.72,20.13
GND  (via drill 0.51)
  Top 0.508: 19.34,48.23 16.2,48.23 15.72,48.71 12.6,48.71 C14.- | 19.34,48.23 19.82,48.71 C22.- | R6.1 73.38,48.05 73.58,48.05 75.12,49.59 75.12,50.19 D7.K 75.12,51.25 75.12,52.51 74.64,52.99 74.64,56.61 v74.78,57.05 | IC2.15 43.84,28.97 43.84,31.11 C8.- 43.48,33.73 v43.54,34.17 | SJ3.2 51.28,59.59 51.34,59.59 v52.14,58.79 52.94,57.99 53.7,57.99 55.3,59.59 SJ2.2 | D12.K 33.34,25.59 33.34,26.45 C18.- 33.72,29.01 35.08,29.01 36.74,30.67 37.42,30.67 39.18,32.43 X4.18 | 80.9,59.89 80.26,59.89 IC4.4 | 80.9,59.89 C11.2 | v31.24,51.55 30.88,51.19 30.64,51.19 C17.2 | SJ4.3 44.32,10.77 44.32,12.55 JP2.1 | IC3.P$22 v57.84,40.91 | IC8.P$8 11.58,29.29 11.58,29.73 11.98,30.13 v12.18,30.57 11.98,31.01 11.98,32.09 C23.- | IC8.P$2 19.2,27.27 19.38,27.09 19.38,27.07 19.64,26.81 21.7,26.81 DC1.1 22.1,27.65 22.1,32.11 C19.- | IC2.8 51.14,20.81 51.14,20.37 50.2,19.43 CON2.P$1 | D13.K 32.2,12.91 31.84,12.91 31.18,13.57 30.06,13.57 27.84,11.35 27.84,9.37 C27.P$1 | v25.04,60.19 C5.- | C20.- v63.88,23.65 | C12.- v76.22,28.43 | v80.94,60.69 80.94,60.13 80.9,59.89 | IC5.P$5 v34.24,38.95 | v29.9,42.35 IC5.P$3 | 19.34,48.23 v19.4,48.15
  GND 0.508: T6.3 50.92,27.95 50.92,29.11 51.12,29.31 51.12,30.29 D16.1 | D15.1 47.94,31.67 48.18,31.67 48.66,32.15 50.36,32.15 50.84,31.67 D16.1 | 56.47,29.78 56.98,30.29 D17.1 56.98,31.67 56.98,33.65 | 56.47,29.78 v56.18,29.49 55.36,28.67 55.36,27.95 T3.3 | 56.98,33.65 55.94,34.69 54.44,34.69 C3.2 | C2.2 62.32,34.69 58.16,34.69 57.22,33.75 56.98,33.65 | D16.1 51.82,31.67 52.04,31.67 52.52,32.15 54.1,32.15 56.47,29.78 | C7.2 38.66,47.63 38.66,47.97 v39.38,48.69 39.86,49.17 39.86,50.91 39.38,51.39 C4.2 | C9.2 37.64,38.29 37.16,37.81 34.48,37.81 T1.3 34.04,38.09 34.04,38.51 v34.24,38.95 | v43.54,34.17 43.54,31.65 D14.1 | v83.6,37.99 T2.3 | v12.18,30.57 12.88,30.57 C13.2 | C15.1 25.78,27.59 24,27.59 DC1.1 | C21.1 50.12,19.43 CON2.P$1 | v48.64,47.19 47.96,47.19 C10.2 | v62.76,58.39 62.08,58.39 C28.2 | v74.78,57.05 75.46,57.05 C6.2 | D9.A 38.92,55.63 40.72,55.63 CON1.P$2 | B2.MINUS 28.36,51.23 30.92,51.23 v31.24,51.55
  pour Route3: 25,0.47 25,15.47 30.2,15.47 30.2,25.67 10.36,25.67 10.36,61.47 89.5,61.47 89.5,0.47
GND-BUS  (via drill 0.51)
  Top 0.406: C16.1 12.74,16.47 v11.98,17.23 11.22,17.99 IC8.P$9 | C24.2 19.9,16.39 19.9,17.29 19.2,17.99 IC8.P$15 19.2,20.01 19.26,20.01 20.9,21.65 21.7,21.65 DC1.3 | C29.- 13.96,3.07 12.7,3.07 R8.1 11.22,3.07 9.66,3.07 HOLE1.P$1 | C25.2 C26.2 21.52,8.99 20.62,8.99 C27.P$2
  GND 0.406: 11.22,5.89 10.97,5.89 9.66,5.89 HOLE1.P$1 | CON3.P$5 8.8,15.95 11.16,15.95
  pour GND: 28.4,22.94 10.35,22.94 10.35,0.45 23.47,0.45 23.47,16.97 28.4,16.97
IN1
  Top 0.559: CON5.P$3 16.68,53.73 17.68,53.73 18.7,52.71 20.88,52.71 21.9,53.73 CON5.P$1
  GND 0.559: B2.WECHSEL1 31.88,58.65 29.1,58.65 26.72,56.27 23.68,56.27 CON5.P$1
IN2
  Top 0.559: CON5.P$4 13.18,56.27 14.18,56.27 15.2,57.29 17.38,57.29 18.4,56.27 CON5.P$2
  GND 0.559: B2.WECHSEL2 26.78,58.65 22.56,58.65 20.18,56.27 CON5.P$2
N$1  (via drill 0.51)
  Top 0.356: v68.74,53.37 68.04,53.37 IC3.P$39
  Route3 0.356: v62.48,41.97 62.48,41.55 61.88,40.95 61.88,36.99 61.66,36.77 61.66,36.27 53.78,28.39 v53.78,22.55
  GND 0.356: R47.1 55.4,13.73 S2.1 55.58,15.45 54.56,16.47 54.24,16.47 53.38,17.33 53.38,19.15 53.78,19.55 v53.78,22.55 | v68.74,53.37 68.7,53.37 61.18,45.85 61.18,43.27 v62.48,41.97
N$2  (via drill 0.51)
  Top 0.356: v62.5,50.93 65.06,50.93 66.28,52.15 IC3.P$38 | v60.82,36.91 62.44,35.29 62.44,24.37 61.48,23.41 61.48,23.31 S2.2 | v59.14,40.91 59.14,41.13 56.54,43.73 v56.32,43.73
  GND 0.356: v62.5,50.93 59.46,50.93 R48.1 59.16,49.65 59.16,46.37 56.52,43.73 v56.32,43.73 | v60.82,36.91 60.82,39.23 v59.14,40.91
N$3  (via drill 0.51)
  Top 0.356: v71.22,48.51 68.9,50.83 68.04,50.83 IC3.P$37 | v76.74,44.77 81.3,40.21 81.3,26.45 77.62,22.77 74.44,22.77 72.86,21.19 67.82,21.19 61.9,15.27 S2.4
  GND 0.356: R49.1 60.9,17.47 60.9,15.69 S2.4 | v71.22,48.51 73,48.51 v76.74,44.77
N$4  (via drill 0.51)
  Top 0.356: v76.8,43.51 76.06,44.25 LED1.C
  GND 0.356: v76.8,43.51 76.8,42.81 R35.2
N$5  (via drill 0.51)
  Top 0.356: v74.78,47.95 74.78,47.03 73.52,45.77 LED2.C
  GND 0.356: v74.78,47.95 74.78,49.35 R10.2
N$6  (via drill 0.51)
  Top 0.356: IC3.P$29 68.04,40.67 69.08,40.67 69.28,40.47 70.82,40.47 71,40.65 v75.54,40.65 75.98,40.45 76.76,40.45 78.6,38.61 78.6,33.55 79.42,32.73 79.42,32.07 OK1.P$6
  GND 0.356: R40.2 81.54,32.35 81,32.35 80.34,31.69 OK1.P$6 | v75.54,40.65 75.54,41.35 R35.1
N$7  (via drill 0.51)
  Top 0.356: v36.86,50.03 36.86,52.99 41.06,57.19 54.12,57.19 54.98,56.33 IC3.P$4
  GND 0.356: v36.86,50.03 34.58,47.75 34.58,43.07 R12.2
N$8
  GND 0.356: R9.1 85.2,19.95 83.98,19.95 83.58,19.55 80.58,19.55 78.7,21.43 JP7.P$3-4
N$9
  Top 0.356: R2.2 11.24,12.99 8.98,12.99 JP5.4
N$10
  GND 0.356: R26.2 85.54,27.61 85.7,27.61 86.68,26.63 OK1.P$1
N$11
  Top 0.356: IC3.P$20 55.62,38.45 55.62,33.89 Q1.1
  GND 0.356: C3.1 54.44,33.57 55.3,33.57 Q1.1
N$12
  Top 0.356: IC3.P$21 56.94,38.45 56.94,37.65 60.7,33.89 Q1.2
  GND 0.356: C2.1 62.32,33.55 61.48,33.55 Q1.2
N$13  (via drill 0.51)
  Top 0.356: v51.96,32.95 53.18,32.95 55.24,30.89 55.24,28.69 D5.A
  GND 0.356: v51.96,32.95 51.28,32.95 R36.1
N$14  (via drill 0.51)
  Top 0.356: v63.52,42.95 61.1,42.95 58.16,45.89 57.96,45.89 54.66,49.19 54.66,54.25 54.36,54.55 IC3.P$5
  Route2 0.356: v66.12,37.79 66.12,39.49 65.2,40.41 65.2,41.27 v63.52,42.95
  GND 0.356: v66.12,37.79 67.96,35.95 70.06,35.95 73.28,32.73 73.28,29.21 71.76,27.69 71.76,26.03 R21.2
N$15  (via drill 0.51)
  Top 0.356: v50.42,23.85 53.68,23.85 54.52,24.69 55.2,24.69 D5.K
  GND 0.356: v50.42,23.85 49.96,24.31 49.96,24.37 T6.2
N$16  (via drill 0.51)
  Top 0.356: v9.9,8.37 11.22,8.37 R3.2
  GND 0.356: v9.9,8.37 4.72,8.37 3.5,9.59 JP1.2
N$17
  GND 0.356: R27.2 85.56,32.31 86.04,32.31 86.66,31.69 OK1.P$3
N$18
  Top 0.356: R8.2 11.22,5.41 6.72,9.91 JP5.1
N$19  (via drill 0.51)
  Top 0.356: v64.36,40.91 64.36,47.69 66.24,49.57 66.28,49.57 IC3.P$36 | v64.66,37.77 64.66,25.63 62.76,23.73 v62.76,23.49
  Route2 0.356: v64.36,40.91 64.36,38.07 v64.66,37.77
  GND 0.356: R50.1 56.14,18.97 56.14,20.47 S2.8 56.82,22.89 57.64,23.71 61.66,23.71 61.88,23.49 v62.76,23.49
N$20  (via drill 0.51)
  Top 0.356: v55.08,23.69 55.62,23.69 56.16,24.23 57.9,24.23 58.3,24.63 59.16,24.63 D6.K
  GND 0.356: v55.08,23.69 54.4,24.37 T3.2
N$21
  GND 0.356: T4.1 65.54,21.85 65.54,22.53 R11.1 64.76,24.01 64.28,24.49 64.14,24.49 R23.1
N$22  (via drill 0.51)
  Top 0.356: v46.58,32.25 46.88,32.25 48.6,30.53 51.74,30.53 55.04,27.23 58.76,27.23 59.16,27.63 D6.A
  GND 0.356: v46.58,32.25 46.58,32.93 R37.1
N$23
  GND 0.356: T3.1 56.3,25.07 57.08,25.07 R38.1 58.56,25.15 59.68,25.15 R39.1
N$24  (via drill 0.51)
  Top 0.356: v41.26,21.09 42.26,21.09 IC2.1 | v45.24,11.53 45.3,11.47 45.3,10.77 SJ4.2
  GND 0.356: R51.2 41.76,21.59 v41.26,21.09 41.7,20.89 43.36,19.23 43.36,12.93 44.76,11.53 v45.24,11.53
N$25  (via drill 0.51)
  Top 0.356: v68.74,42.15 68.04,42.15 IC3.P$30
  GND 0.356: SW1.P$2 82.58,13.13 80,15.71 80,15.85 R33.1 78.72,17.01 77,18.73 77,19.17 75.94,20.23 75.5,20.23 74.46,21.27 74.46,22.15 75.06,22.75 75.06,24.01 74.82,24.25 74.82,32.79 73.9,33.71 73.9,39.71 71.46,42.15 v68.74,42.15
N$26
  GND 0.356: 32.68,39.83 32.68,37.89 32.28,37.49 32.28,37.15 T1.1 | 32.68,39.83 32.42,40.09 R16.2 | R12.1 33.1,40.09 32.84,39.83 32.68,39.83
N$27  (via drill 0.51)
  Top 0.356: v52.7,51.01 51.98,50.29 51.94,50.29 IC3.P$10 | v56.86,57.01 56.86,58.33 57.9,59.37 D1.C | v63.5,60.21 64.18,60.21 D2.C
  GND 0.356: v52.7,51.01 52.7,52.85 v56.86,57.01 56.84,57.45 59.6,60.21 v63.5,60.21
N$28  (via drill 0.51)
  Top 0.356: v84.72,38.35 84.72,37.05 R22.1 84.98,36.57 87.34,36.57 SJ1.1
  GND 0.356: v84.72,38.35 84.72,40.89 T2.2
N$29
  Top 0.356: R6.2 72.64,50.47 C1.- 72.04,52.39 67.06,57.37 65.56,57.37 63.56,59.37 62.68,59.37 D1.A
N$30
  GND 0.356: R19.1 72.04,15.23 71.14,15.23 D3.AR
N$31
  GND 0.356: R17.1 64.26,17.39 64.74,16.91 D3.AG
N$32
  GND 0.356: T6.1 51.26,24.37 51.26,23.49 50.78,23.01 46.36,23.01 44.7,24.67 R1.1 44.7,26.13 45.38,26.81 45.38,29.61 45.12,29.87 44.76,29.87 44.54,30.09 44.54,34.69 46.48,36.63 46.48,38.57 R4.1
N$34
  GND 0.356: R18.1 72.04,12.17 70.9,11.03 D4.AR
N$35  (via drill 0.51)
  Top 0.356: v63.24,41.11 62.14,41.11 57.92,45.33 57.72,45.33 54.1,48.95 54.1,53.53 53.08,54.55 IC3.P$6
  Route2 0.356: v63.32,32.25 63.32,36.03 63.76,36.47 63.76,40.31 63.24,40.83 v63.24,41.11
  GND 0.356: v63.32,32.25 63.32,27.45 R23.2
N$36
  Top 0.356: D2.A 68.96,60.23 72.12,60.23 IC4.5
N$37
  GND 0.356: T2.1 82.16,40.89 82.16,40.09 R15.2 81.52,37.45 R14.1
N$38  (via drill 0.51)
  Top 0.356: v69.86,53.37 69.86,53.45 68.76,54.55 65.82,54.55 IC3.P$40 | v72.14,9.41 70.9,8.17 58.48,8.17 56.82,9.83 S1.8
  GND 0.356: R32.1 53.64,10.81 55.4,10.81 S1.8 | v69.86,53.37 73.48,53.37 78.86,47.99 78.86,44.07 80.26,42.67 85.22,42.67 88.36,39.53 88.36,15.87 83.58,11.09 73,11.09 72.14,10.23 v72.14,9.41
N$39
  Top 0.356: C16.2 15.56,15.01 15.56,14.77 16.04,14.29 16.86,14.29 17.32,13.83 D11.A 18.68,13.83 20.66,13.83 21.74,14.91 C24.1 | C24.1 22.24,18.71 DC1.4 21.7,19.11 20.48,19.11 IC8.P$16 | C29.+ 21.54,3.91 22.52,3.91 23.4,4.79 23.4,14.39 22.88,14.91 C24.1
N$40
  GND 0.356: T7.1 72.1,37.17 71.1,37.17 R7.1 69.96,37.83 69.4,38.39 69.4,39.15 R5.1
N$41
  GND 0.356: R20.1 64.26,11.19 64.74,10.71 D4.AG
N$42  (via drill 0.51)
  Top 0.356: v56.08,42.61 51.94,42.61 IC3.P$16 | v69.72,55.91 71.16,57.35 72.12,57.35 IC4.7
  GND 0.356: v56.08,42.61 56.42,42.61 v69.72,55.91
N$43  (via drill 0.51)
  Top 0.356: v64.56,53.87 64.56,54.55 IC3.P$41 | v89.12,43.01 89.12,39.05 89.32,38.85 89.32,35.81 88.52,35.01 86.88,35.01 86.26,34.39 86.26,30.97 87.3,29.93 87.74,29.93 88.36,29.31 88.36,24.11 80.26,16.01 78.98,16.01 75.22,12.25 75.22,5.25 74.38,4.41 68.06,4.41 67.72,4.75 62.46,4.75 61.9,4.19 S1.4
  GND 0.356: R31.1 62.74,6.25 62.74,5.87 61.48,4.61 S1.4 | v64.56,53.87 64.56,55.61 66.32,57.37 73.26,57.37 75.34,55.29 80.52,55.29 89.12,46.69 v89.12,43.01
N$44  (via drill 0.51)
  Top 0.356: v78.18,53.89 77.28,53.89 D7.A
  GND 0.356: v78.18,53.89 78.18,53.21 R34.1
N$45  (via drill 0.51)
  Top 0.356: v66.68,56.53 66.48,56.73 63.64,56.73 63.28,56.37 63.28,56.33 IC3.P$42 | v73.36,10.25 72.26,10.25 70.9,11.61 61.9,11.61 S1.2
  GND 0.356: R30.1 59.2,7.73 60.9,9.43 S1.2 | v66.68,56.53 69.14,56.53 69.36,56.75 70.08,56.75 70.6,56.23 70.6,56.05 71.92,54.73 80.22,54.73 84.14,50.81 84.14,44.55 88.92,39.77 88.92,15.63 83.54,10.25 v73.36,10.25
N$46  (via drill 0.51)
  Top 0.356: v63.52,44.49 63.52,45.19 61.66,47.05 61.66,54.55 IC3.P$43 | v72.68,18.39 72.68,14.51 v70.64,12.47
  Route3 0.356: v63.52,44.49 72.24,35.77 v72.24,34.97
  GND 0.356: R29.1 53.62,3.19 55.4,3.19 S1.1 56.82,2.21 57.64,1.39 61.66,1.39 69,8.73 69,10.55 70.64,12.19 v70.64,12.47 | v72.24,34.97 72.24,34.57 73.84,32.97 73.84,24.47 72.68,23.31 v72.68,18.39
N$47
  GND 0.356: T5.1 69.12,22.55 R13.1 69.42,24.01 R21.1
N$48  (via drill 0.51)
  Top 0.356: v79.34,15.17 v84.02,15.17
  GND 0.356: T5.3 70.56,18.29 71.58,18.29 73.92,15.95 R19.2 | R18.2 R19.2 | v84.02,15.17 84.54,15.69 84.54,15.85 R28.1 | v79.34,15.17 75.02,15.17 R19.2
N$49
  GND 0.356: T7.3 75.38,37.63 75.38,30.47 78.64,27.21 78.64,25.89 81.2,23.33 84.78,23.33 85.2,22.91 R9.2
N$50  (via drill 0.51)
  Top 0.356: v77.04,35.61 76.64,35.61 76.58,35.67 75.1,35.67 D18.A 73.32,36.73 72.22,36.73 68.96,39.99 v66.82,39.99 | v48.28,45.83 47.8,46.31 47.8,49.25 49.38,50.83 50.18,50.83 IC3.P$9 | v52.64,41.47 56.8,41.47 v57.04,41.71
  GND 0.356: v77.04,35.61 77.04,35.91 79.18,38.05 79.18,38.61 R15.1 | v52.64,41.47 v48.28,45.83 | v57.04,41.71 57.44,41.71 57.58,41.85 61.4,41.85 62.4,40.85 62.4,40.75 63.16,39.99 v66.82,39.99
N$51
  Top 0.356: 86.82,39.19 83.6,39.19 82.76,38.35 82.76,37.05 R22.2 | 86.82,39.19 87.34,38.67 SJ1.2 | 86.82,39.19 86.9,39.35 86.9,44.23 SG2.P$2-
  GND 0.356: D10.A 85.92,47.55 86.98,46.49 SG2.P$2-
N$52  (via drill 0.51)
  Top 0.356: v81.26,20.63 68.88,20.63 v67.9,19.65
  GND 0.356: R20.2 62.78,14.15 62.78,16.79 62.38,17.19 62.38,18.85 62.78,19.25 R17.2 64.26,19.09 66,19.09 T4.3 66.96,19.65 v67.9,19.65 | v81.26,20.63 81.94,20.63 R25.1
N$53  (via drill 0.51)
  Top 0.356: v61.04,41.01 53.54,48.51 53.54,51.83 51.94,53.43 IC3.P$7
  GND 0.356: v61.04,41.01 62.9,39.15 66.86,39.15 68.12,37.89 68.12,37.83 R7.2
N$54  (via drill 0.51)
  Top 0.356: v53.32,58.91 53.32,59.59 SJ2.1 | v52.7,49.63 52.7,48.55 60.02,41.23 60.02,40.23 IC3.P$24
  GND 0.356: v53.32,58.91 53.32,54.27 51.86,52.81 51.86,50.47 v52.7,49.63
N$55  (via drill 0.51)
  Top 0.356: v49.44,58.91 49.44,59.59 SJ3.1 | v59.82,37.77 60.64,37.77 61.32,38.45 IC3.P$25
  GND 0.356: v49.44,58.91 49.44,49.85 55.24,44.05 55.24,42.25 59.72,37.77 v59.82,37.77
N$56  (via drill 0.51)
  Top 0.356: v51.72,39.99 52.4,39.99 IC3.P$18 | v18.58,31.21 16.66,29.29 IC8.P$4
  GND 0.356: v51.72,39.99 51.72,40.93 46.52,46.13 46.3,46.13 45.02,47.41 45.02,52.35 42.9,54.47 42.9,56.43 42.14,57.19 32.16,57.19 22.62,47.65 22.62,35.25 v18.58,31.21
N$57  (via drill 0.51)
  Top 0.356: 47.98,24.67 47.98,22.83 IC2.5 | 47.98,24.67 v47.98,26.27 | R42.2 33.72,18.07 34.54,18.07 35.86,19.39 35.86,19.53 36.92,20.59 37.38,20.59 39.12,22.33 X4.10 39.18,23.55 38.4,24.33 38.4,25.87 39.02,26.49 39.9,26.49 40.64,25.75 42.6,25.75 43.68,24.67 47.98,24.67
  GND 0.356: v47.98,26.27 47.98,28.11 D15.3
N$58
  GND 0.356: R25.2 81.94,22.77 76.94,22.77 76.16,21.99 JP7.P$2-3
N$59
  Top 0.356: IC2.2 43.52,22.83 43.52,24.03 42.36,25.19 40.12,25.19 X4.12
  GND 0.356: D14.3 44,28.09 42.5,28.09 40.12,25.71 X4.12
N$60  (via drill 0.51)
  Top 0.356: v66.56,27.15 68.66,25.05 68.66,23.39 61.36,16.09 55.42,16.09 48.1,8.77 43.58,8.77 43.32,9.03 v43.32,11.37 | v62.92,37.77 IC3.P$26
  GND 0.356: v62.92,37.77 62.92,37.59 64.72,35.79 64.72,28.99 v66.56,27.15 | v43.32,11.37 42.32,12.37 JP2.2
N$61  (via drill 0.51)
  Top 0.356: v62.7,36.61 62.96,36.61 63.82,37.47 63.82,38.45 IC3.P$27 | v48.3,36.41 47.66,36.41 46.82,35.57 42.92,35.57 40.52,33.17 40.52,30.09 39.46,29.03 39.02,29.03 37.98,27.99 37.98,26.29 36.92,25.23 36.48,25.23 35.5,24.25 v35.5,20.37
  GND 0.356: v62.7,36.61 61.72,36.61 60.56,35.45 55.48,35.45 54.52,36.41 v48.3,36.41 | v35.5,20.37 35.5,19.03 36.48,18.05 38.2,18.05 39.02,18.87 41.54,18.87 JP3.2
N$62
  GND 0.356: T1.2 30.9,38.57 29.8,38.57 K1.16 28.3,39.43 27.7,40.03 D8.A
N$63
  GND 0.356: X3.1 27.38,3.65 28.04,3.65 28.84,2.85 37.32,2.85 38.38,3.91 38.38,4.35 39.42,5.39 41.12,5.39 42.18,6.45 42.18,6.89 45.26,9.97 46.72,9.97 49.3,12.55 50.72,12.55 51.36,13.19 51.36,14.67 50.54,15.49 CON2.P$2
N$64
  GND 0.356: R28.2 82.84,17.33 82.84,17.43 81.38,18.89 78.7,18.89 JP7.P$4-1
N$65  (via drill 0.51)
  Top 0.356: 35.02,14.13 34.54,14.61 33.74,14.61 R45.1 | 35.02,14.13 35.02,8.15 33.66,6.79 X3.6 | v52.86,26.15 51.52,26.15 49.24,23.87 49.24,22.83 IC2.6 | v52.66,22.59 52.66,19.39 50.9,17.63 46.64,17.63 45.26,16.25 41.78,16.25 41.7,16.33 39.02,16.33 38.2,15.51 36.92,15.51 35.62,14.21 35.18,14.21 35.02,14.13
  GND 0.356: D17.3 57.92,28.09 57.1,28.09 55.76,26.75 55.76,26.39 55.52,26.15 v52.86,26.15 52.66,25.71 v52.66,22.59
N$66  (via drill 0.51)
  Top 0.356: v44.42,23.75 44.42,23.21 44.8,22.83 IC2.3 | v35.86,8.19 34.56,6.89 34.56,6.43 32.38,4.25 X3.5 | v41.7,10.95 43.68,12.93 43.68,14.97 44.32,15.61 v45.82,15.61
  Route2 0.356: v46.6,25.51 44.84,23.75 v44.42,23.75
  GND 0.356: v46.6,25.51 46.6,28.75 47.74,29.89 49.08,29.89 49.3,29.67 49.3,26.63 49.76,26.17 51.1,26.17 51.8,26.87 51.8,28.09 D16.3 | v35.86,8.19 38.94,8.19 v41.7,10.95 | v45.82,15.61 45.82,16.81 45.9,16.89 45.9,22.47 44.84,23.53 v44.42,23.75
N$67
  Top 0.508: SJ6.2 46.8,2.19 46.8,2.55 45.64,3.71 45.64,4.99 44.36,6.27 44.36,6.93 39.68,11.61 39,11.61 37.22,13.39 X4.3
N$68  (via drill 0.51)
  Top 0.356: v48.72,10.77 47.94,10.77 SJ4.1
  GND 0.356: v48.72,10.77 49.42,10.77 R52.2
N$69
  Top 0.356: R43.2 33.12,20.91 33.12,21.53 D12.A
N$70  (via drill 0.51)
  Top 0.356: v30.8,21.87 30.8,20.91 R43.1
  GND 0.356: v30.8,21.87 30.8,25.65 31.78,26.63 32.48,26.63 T8.3
N$71  (via drill 0.51)
  Top 0.356: v34.18,18.91 32.38,18.91 32.02,18.55 32.02,18.39 R42.1
  GND 0.356: T8.1 33.92,22.57 R24.1 34.18,21.09 v34.18,18.91
N$72  (via drill 0.51)
  Top 0.356: v78.5,39.91 80.74,37.67 80.74,30.97 80.12,30.35 79.26,30.35 78.04,31.57 78.04,35.81 77.66,36.19 77.66,36.29 SJ7.2 | v62.02,45.49 59.56,45.49 v58.32,46.73 | v50.28,54.79 47.24,51.75 47.24,44.21 v47.28,44.17
  GND 0.356: v78.5,39.91 76,39.91 75.9,39.81 74.6,39.81 68.92,45.49 v62.02,45.49 | v58.32,46.73 53.74,46.73 50.28,50.19 v50.28,54.79 | v47.28,44.17 47.28,42.91 41.26,36.89 41.26,32.69 39.74,31.17 X4.16
N$73  (via drill 0.51)
  Top 0.356: v33.82,8.15 33.82,8.87 D13.A
  GND 0.356: R44.1 v33.82,8.15
N$74
  GND 0.356: X3.2 28.64,6.17 29.32,6.17 30.1,5.39 38.58,5.39 39.64,6.45 39.64,6.89 43.28,10.53 45.44,10.53 48.22,13.31 CON2.P$3
N$75
  GND 0.356: T9.3 32.48,16.75 31.78,16.75 29.96,14.93 29.96,11.83 31.48,10.31 R44.2
N$76
  Top 0.356: OK1.P$4 87.58,33.29 87.58,32.63 88.92,31.29 88.92,18.87 84.34,14.29 82.94,14.29 77.7,9.05 X5.2
N$77
  Top 0.356: OK1.P$2 87.04,28.21 87.04,27.55 82.1,22.61 82.1,20.25 74.2,12.35 74.2,9.05 X5.1
N$78  (via drill 0.51)
  Top 0.356: v34.18,13.77 32.42,13.77 32.04,14.15 32.04,14.31 R45.2
  GND 0.356: 33.92,13.77 33.92,13.09 R46.2 | 33.92,13.77 T9.1 | v34.18,13.77 33.92,13.77
N$79  (via drill 0.51)
  Top 0.356: v43.96,20.13 40.72,20.13 39.9,19.31 v38.26,19.31
  GND 0.356: v43.96,20.13 43.96,21.59 R51.1 | v38.26,19.31 38.2,19.31 36.92,20.59 36.48,20.59 35.86,21.21 35.86,30.37 36.64,31.15 X4.17
N$80
  Top 0.356: R2.1 12.7,12.07 13.92,12.07 D11.C
N$81
  Top 0.356: SJ7.1 76.08,38.75 75.1,38.75 D18.C
RX/TX  (via drill 0.51)
  Top 0.356: v50.32,39.99 50.32,40.67 IC3.P$17 | v48.64,38.31 48.64,38.19 46.58,36.13 41.48,36.13 39.46,34.11 38.18,34.11 36.92,32.85 34.32,32.85 27.4,25.93 16.74,25.93 15.4,27.27 IC8.P$5
  GND 0.356: v48.64,38.31 v50.32,39.99
RXD  (via drill 0.51)
  Top 0.356: v61.16,30.55 61.16,31.11 61.88,31.83 61.88,34.41 v58.68,37.61 | v54.16,43.93 54.16,46.13 51.94,48.35 IC3.P$11 50.18,48.81 v49.4,48.03 | v18.62,29.97 17.94,29.29 IC8.P$3
  Route2 0.356: v35.52,35.27 48.28,48.03 v49.4,48.03
  GND 0.356: v61.16,30.55 61.16,27.47 R39.2 | v58.68,37.61 58.68,38.01 54.16,42.53 v54.16,43.93 | v18.62,29.97 25.52,29.97 30.82,35.27 v35.52,35.27
S1  (via drill 0.51)
  Top 0.66: v36.84,58.51 35.96,58.51 35.88,58.59 L1.2 34.18,58.59 v34.18,51.61 | v33.56,46.95 33.56,46.27 IC5.P$1
  GND 0.66: v36.84,58.51 36.84,59.19 D9.C | v33.56,46.95 33.56,47.75 34.18,48.37 v34.18,51.61
TXD  (via drill 0.51)
  Top 0.356: v47.96,42.23 47.96,43.59 50.18,45.81 IC3.P$13 | v38.06,36.11 17.54,36.11 14.12,32.69 14.12,29.29 IC8.P$6
  Route2 0.356: v38.06,36.11 43.98,42.03 47.52,42.03 v47.96,42.23
  GND 0.356: v47.96,42.23 47.96,41.55 R4.2
VCC  (via drill 0.51)
  Top 0.508: IC3.P$35 68.04,48.29 68.2,48.29 71.26,45.23 71.26,43.41 71.74,42.93 LED2.A | LED1.A 74.28,42.15 73.52,42.15 LED2.A | IC8.P$1 19.86,29.29 19.86,31.29 19.06,32.09 C23.+ 16.74,32.09 16.74,31.01 v16.54,30.57 | C19.+ 28.78,33.31 v30.06,33.31 31.34,33.31 C18.+ | C11.1 80.9,57.67 80.26,57.67 IC4.2 79.26,57.99 79.26,58.63 IC4.3 78.26,59.27 75.12,59.27 v74.78,59.57 | C1.+ 72.62,56.09 IC4.8 72.12,56.41 v71.44,56.41 | v44.5,1.39 SJ6.1 | v60.38,53.87 IC3.P$44 | v42.58,29.65 42.58,28.97 IC2.16 | C8.+ 51.16,31.17 53.52,31.17 53.96,30.73 v54.4,30.53 | C20.+ v74.22,23.65 | v76.22,34.83 C12.+ | L1.1 33.12,48.03 31.14,48.03 30.36,47.25 29.8,47.25 K1.1 | IC5.P$4 35.08,40.65 v35.52,40.45 | LED2.A 71.74,41.51 70.9,41.51 v70.46,41.31
  GND 0.508: 51.7,9.11 52.16,9.11 R32.2 52.88,8.47 v52.88,7.01 52.88,6.99 | 51.7,9.11 50.88,9.11 R52.1 | 52.88,6.99 52.88,5.53 R29.2 | R47.2 52.88,14.85 52.66,14.85 52,14.19 52,11.97 51.7,11.67 51.7,9.11 | 52.88,6.99 56.22,6.99 R30.2 57.24,6.25 57.72,5.77 59.4,5.77 59.88,6.25 61.04,6.25 R31.2 | 83.58,26.55 83,26.55 R41.1 | 83.58,26.55 R26.1 | 83.35,32 83.02,31.67 R40.1 | 83.35,32 83.5,32.15 83.5,33.83 83.22,34.11 82.04,34.11 80.4,35.75 80.4,35.99 R14.2 79.18,35.99 78.72,35.99 77.42,34.69 76.66,34.69 v76.22,34.83 | 83.35,32 83.52,31.83 84.08,31.83 R27.1 84.08,30.61 83.58,30.11 83.58,26.55 | DC1.2 24.28,24.77 25.06,25.55 25.7,25.55 27.52,27.37 27.52,27.59 C15.2 28.74,29.07 28.74,31.75 29.86,32.87 v30.06,33.31 | D14.2 45.66,31.65 v45.66,32.93 45.66,34.21 46.36,34.91 R37.2 47.82,35.29 49.8,35.29 R36.2 | 59.1,54.07 59.1,57.65 C28.1 | 59.1,54.07 59.1,52.63 R48.2 | R34.2 81.16,51.73 81.16,49.31 D10.C 81.16,47.55 80.38,46.77 SG2.P$1+ | 59.38,29.35 59.38,27.87 58.56,27.05 R38.2 | 59.38,29.35 59.38,30.29 D17.2 | C7.1 36.9,47.63 36.9,48.39 v37.42,48.91 37.92,49.41 C4.1 | R50.2 55.02,17.51 55.02,17.27 55.26,17.03 v57.26,17.03 57.68,17.03 58.12,17.47 R49.2 | 32.02,23.51 32.02,22.57 R24.2 | 32.02,23.51 T8.2 | T7.2 72.1,39.15 71.1,39.15 R5.2 v70.46,41.31 | T9.2 32.02,13.09 R46.1 31.48,12.65 v30.8,12.65 | T4.2 67.44,21.85 67.44,22.53 R11.2 67.74,24.01 67.74,24.61 v67.82,24.69 | R13.2 71.02,22.55 T5.2 71.24,20.49 v71.24,19.79 | v54.4,30.53 53.72,30.53 D16.2 | v50.2,29.69 49.84,30.05 49.84,30.31 D15.2 | v16.54,30.57 15.84,30.57 C13.1 | v42.38,23.97 42.38,24.67 R1.2 | R16.1 30.94,43.07 29.34,44.67 K1.1 28.58,44.81 27.7,44.81 D8.C
  GND 0.508: v51.82,19.75 C21.2 | v35.52,40.45 35.68,40.29 35.68,39.77 C9.1 | v48.64,48.89 47.96,48.89 C10.1 | v81.06,18.01 81.06,17.33 R33.2 | v74.78,59.57 75.46,59.57 C6.1 | 32.02,23.51 v33,23.51 | 59.38,29.35 v59.58,29.35 | 59.1,54.07 59.94,54.07 v60.38,53.87
  pour Route2: 25,0.47 25,15.47 30.2,15.47 30.2,25.67 10.25,25.67 10.25,61.47 89.5,61.47 89.5,0.47

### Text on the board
Top: CH | MI | 5V-Chip
GND: UNI-CR-485 04.03.05 HK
